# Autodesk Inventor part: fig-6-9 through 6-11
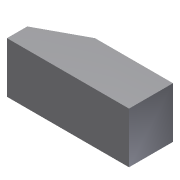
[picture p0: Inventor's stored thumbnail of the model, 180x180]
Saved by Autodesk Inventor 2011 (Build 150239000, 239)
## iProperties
Created: 2009-09
Part Number: fig-6-9 through 6-11
Document SubType Name: Modeling
Designer: Sham
Density: 1 g/cm^3
Author: Sham
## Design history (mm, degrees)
sketch "Sketch1"
  geometry: L1 (-40, 0)-(-40, 12); L2 (-40, 12)-(-14, 26); L3 (-14, 26)-(32.108, 26); L4 (-40, 0)-(32.108, 0); L5 (32.108, 0)-(32.108, 26)
  constraints: 10 end point, 3 perpendicular
extrude "Extrusion1" new body sketch "Sketch1" distance "d0" = 30; taper "d1" = 0 deg
hole "Hole1" diameter "d4" = 10; stored, may be unused: countersink angle "d8" = 90 deg, drill point angle "d10" = 118 deg; dims "d2" = 15, "d3" = 16, "d5" = 6, "d6" = 15, "d7" = 5, "d9" = 12
hole "Hole2" diameter "d13" = 10; stored, may be unused: countersink angle "d17" = 90 deg, drill point angle "d19" = 118 deg; dims "d11" = 12, "d12" = 15, "d14" = 6, "d15" = 15, "d16" = 2, "d18" = 15
hole "Hole3" diameter "d22" = 10; stored, may be unused: countersink angle "d26" = 90 deg, drill point angle "d28" = 118 deg; dims "d20" = 15, "d21" = 15, "d23" = 6, "d24" = 15, "d25" = 2, "d27" = 15
body "Solid1"
